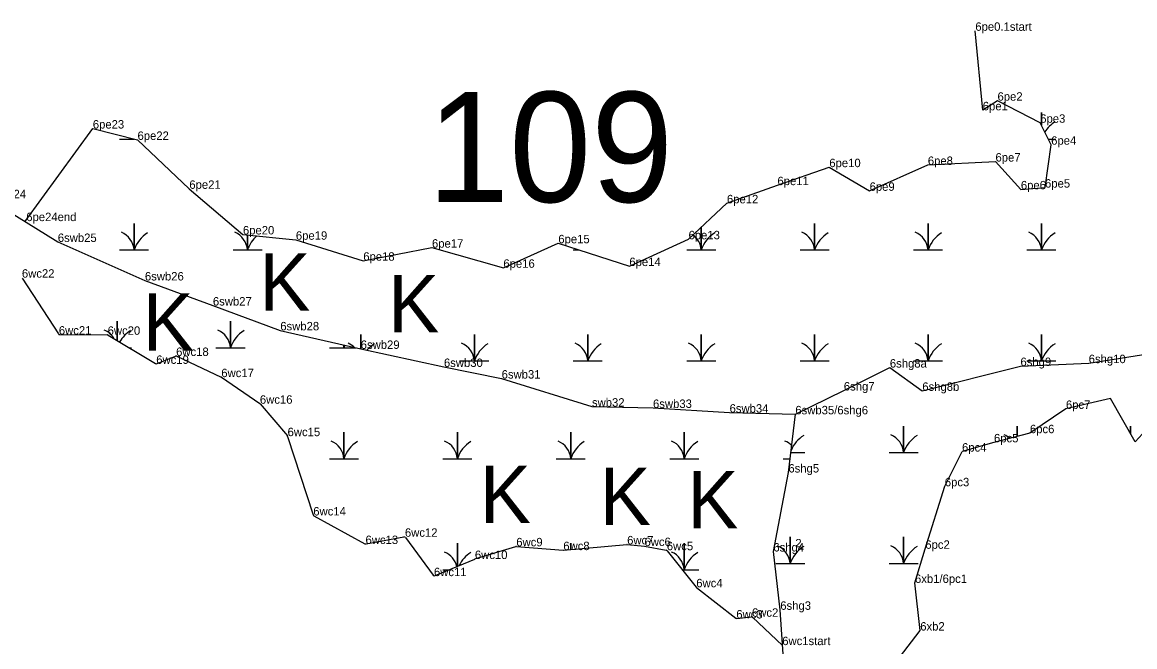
# Model space of a CAD drawing. Extents: x 2072529 to 2268796, y 436423 to 470406.
# Drawn here: x 2142381 to 2143041, y 445096 to 445467 of the extents above; entities that cross this region are included whole.
import ezdxf

# ---------------------------------------------------------------- set-up
doc = ezdxf.new("R2010")
doc.units = 0
for name, color, linetype in [('Default', 7, 'Continuous'), ('Exist Environmental Wetland Boundary Cogo Comment', 7, 'Continuous'), ('Exist Environmental Wetland Boundary Cogo Point CELL', 7, 'Continuous'), ('Exist Hydro Jurisdictional Stream or Body of Water NEU Mitigable Cogo Comment', 7, 'Continuous'), ('Old_Level_20', 7, 'Continuous'), ('Old_Level_52', 7, 'Continuous')]:
    doc.layers.add(name, color=color, linetype=linetype)

msp = doc.modelspace()

# ---------------------------------------------------------------- linework, layer by layer
at = {"layer": 'Exist Environmental Wetland Boundary Cogo Point CELL'}
for points in [[(2142985.22, 445405.66), (2142985.22, 445413.26), (2142985.22, 445405.66)], [(2142438.62, 445397.48), (2142447.22, 445397.48)], [(2142989.29, 445397.48), (2142993.82, 445397.48)], [(2142438.62, 445331.68), (2142447.22, 445331.68), (2142447.22, 445347.46), (2142447.22, 445331.68), (2142455.82, 445331.68)], [(2142774.87, 445331.68), (2142783.47, 445331.68), (2142783.47, 445345.08)], [(2142783.47, 445345.08), (2142783.47, 445331.68), (2142792.07, 445331.68)], [(2142842.12, 445331.68), (2142850.72, 445331.68), (2142850.72, 445347.46), (2142850.72, 445331.68), (2142859.32, 445331.68)], [(2142909.37, 445331.68), (2142917.97, 445331.68), (2142917.97, 445347.46), (2142917.97, 445331.68), (2142926.57, 445331.68)], [(2142976.62, 445331.68), (2142985.22, 445331.68), (2142985.22, 445347.46), (2142985.22, 445331.68), (2142993.82, 445331.68)], [(2142505.87, 445331.68), (2142514.47, 445331.68), (2142514.47, 445340.62)], [(2142514.47, 445340.62), (2142514.47, 445331.68), (2142523.07, 445331.68)], [(2142707.62, 445331.68), (2142711.16, 445331.68)], [(2142437.12, 445278.04), (2142437.12, 445289.47), (2142437.12, 445278.04)], [(2142495.77, 445273.69), (2142504.37, 445273.69), (2142504.37, 445289.47), (2142504.37, 445273.69), (2142512.97, 445273.69)], [(2142581.72, 445272.99), (2142581.72, 445281.66), (2142581.72, 445272.99)], [(2142640.37, 445265.88), (2142648.97, 445265.88), (2142648.97, 445281.66), (2142648.97, 445265.88), (2142657.57, 445265.88)], [(2142707.62, 445265.88), (2142716.22, 445265.88), (2142716.22, 445281.66), (2142716.22, 445265.88), (2142724.82, 445265.88)], [(2142774.87, 445265.88), (2142783.47, 445265.88), (2142783.47, 445281.66), (2142783.47, 445265.88), (2142792.07, 445265.88)], [(2142842.12, 445265.88), (2142850.72, 445265.88), (2142850.72, 445281.66), (2142850.72, 445265.88), (2142859.32, 445265.88)], [(2142909.37, 445265.88), (2142917.97, 445265.88), (2142917.97, 445281.66), (2142917.97, 445265.88), (2142926.57, 445265.88)], [(2142976.62, 445265.88), (2142985.22, 445265.88), (2142985.22, 445281.66), (2142985.22, 445265.88), (2142993.82, 445265.88)], [(2142444.4, 445273.69), (2142445.72, 445273.69)], [(2142563.02, 445273.69), (2142571.62, 445273.69), (2142571.62, 445275.32)], [(2142571.62, 445275.32), (2142571.62, 445273.69), (2142578.7, 445273.69)], [(2142894.87, 445211.51), (2142903.47, 445211.51), (2142903.47, 445227.29), (2142903.47, 445211.51), (2142912.07, 445211.51)], [(2142970.72, 445221.08), (2142970.72, 445227.29), (2142970.72, 445221.08)], [(2143037.97, 445222.71), (2143037.97, 445227.29), (2143037.97, 445222.71)], [(2142563.02, 445207.89), (2142571.62, 445207.89), (2142571.62, 445223.67), (2142571.62, 445207.89), (2142580.22, 445207.89)], [(2142630.27, 445207.89), (2142638.87, 445207.89), (2142638.87, 445223.67), (2142638.87, 445207.89), (2142647.47, 445207.89)], [(2142697.52, 445207.89), (2142706.12, 445207.89), (2142706.12, 445223.67), (2142706.12, 445207.89), (2142714.72, 445207.89)], [(2142764.77, 445207.89), (2142773.37, 445207.89), (2142773.37, 445223.67), (2142773.37, 445207.89), (2142781.97, 445207.89)], [(2142836.56, 445211.51), (2142844.82, 445211.51)], [(2142832.02, 445207.89), (2142836.12, 445207.89)], [(2142827.62, 445145.71), (2142836.22, 445145.71), (2142836.22, 445161.49), (2142836.22, 445145.71), (2142844.82, 445145.71)], [(2142894.87, 445145.71), (2142903.47, 445145.71), (2142903.47, 445161.49), (2142903.47, 445145.71), (2142912.07, 445145.71)], [(2142638.87, 445144.06), (2142638.87, 445157.87), (2142638.87, 445144.06)], [(2142706.12, 445154.08), (2142706.12, 445157.87), (2142706.12, 445154.08)], [(2142772.23, 445142.09), (2142773.37, 445142.09), (2142773.37, 445157.87), (2142773.37, 445142.09), (2142781.97, 445142.09)], [(2142630.27, 445142.09), (2142634.17, 445142.09)]]:
    msp.add_lwpolyline(points, dxfattribs=at)
for centre, radius, start, end in [((2143003.46, 445391.42), 19.22, 122.12745, 147.76598), ((2142434.95, 445330.79), 12.3, 4.14034, 67.53497), ((2142465.46, 445325.62), 19.22, 122.12745, 161.62219), ((2142502.2, 445330.79), 12.3, 4.14034, 67.53497), ((2142532.71, 445325.62), 19.22, 131.26844, 161.62219), ((2142771.2, 445330.79), 12.3, 4.14034, 52.66995), ((2142801.71, 445325.62), 19.22, 122.12745, 161.62219), ((2142838.45, 445330.79), 12.3, 4.14034, 67.53497), ((2142868.96, 445325.62), 19.22, 122.12745, 161.62219), ((2142905.7, 445330.79), 12.3, 4.14034, 67.53497), ((2142936.21, 445325.62), 19.22, 122.12745, 161.62219), ((2142972.95, 445330.79), 12.3, 4.14034, 67.53497), ((2143003.46, 445325.62), 19.22, 122.12745, 161.62219), ((2142424.86, 445272.8), 12.3, 30.50388, 67.53497), ((2142455.36, 445267.63), 19.22, 122.12745, 150.3865), ((2142492.11, 445272.8), 12.3, 4.14034, 67.53497), ((2142522.61, 445267.63), 19.22, 122.12745, 161.62219), ((2142559.36, 445272.8), 12.3, 4.14034, 12.09595), ((2142589.86, 445267.63), 19.22, 156.83207, 161.62219), ((2142569.45, 445264.99), 12.3, 46.08996, 67.53497), ((2142599.96, 445259.82), 19.22, 122.12745, 139.82345), ((2142636.7, 445264.99), 12.3, 4.14034, 67.53497), ((2142667.21, 445259.82), 19.22, 122.12745, 161.62219), ((2142703.95, 445264.99), 12.3, 4.14034, 67.53497), ((2142734.46, 445259.82), 19.22, 122.12745, 161.62219), ((2142771.2, 445264.99), 12.3, 4.14034, 67.53497), ((2142801.71, 445259.82), 19.22, 122.12745, 161.62219), ((2142838.45, 445264.99), 12.3, 4.14034, 67.53497), ((2142868.96, 445259.82), 19.22, 122.12745, 161.62219), ((2142905.7, 445264.99), 12.3, 4.14034, 67.53497), ((2142936.21, 445259.82), 19.22, 122.12745, 161.62219), ((2142972.95, 445264.99), 12.3, 4.14034, 67.53497), ((2143003.46, 445259.82), 19.22, 122.12745, 161.62219), ((2142559.36, 445207), 12.3, 4.14034, 67.53497), ((2142589.86, 445201.83), 19.22, 122.12745, 161.62219), ((2142626.61, 445207), 12.3, 4.14034, 67.53497), ((2142657.11, 445201.83), 19.22, 122.12745, 161.62219), ((2142693.86, 445207), 12.3, 4.14034, 67.53497), ((2142724.36, 445201.83), 19.22, 122.12745, 161.62219), ((2142761.11, 445207), 12.3, 4.14034, 67.53497), ((2142791.61, 445201.83), 19.22, 122.12745, 161.62219), ((2142828.36, 445207), 12.3, 44.98177, 67.53497), ((2142854.46, 445205.45), 19.22, 122.12745, 157.4262), ((2142891.21, 445210.62), 12.3, 4.14034, 67.53497), ((2142921.71, 445205.45), 19.22, 122.12745, 161.62219), ((2142958.46, 445210.62), 12.3, 49.6148, 67.53497), ((2142626.61, 445141.2), 12.3, 12.88474, 67.53497), ((2142657.11, 445136.03), 19.22, 122.12745, 153.96221), ((2142761.11, 445141.2), 12.3, 4.14034, 67.53497), ((2142791.61, 445136.03), 19.22, 122.12745, 161.62219), ((2142823.96, 445144.82), 12.3, 4.14034, 67.53497), ((2142854.46, 445139.65), 19.22, 122.12745, 161.62219), ((2142891.21, 445144.82), 12.3, 4.14034, 67.53497), ((2142921.71, 445139.65), 19.22, 122.12745, 161.62219)]:
    msp.add_arc(centre, radius, start, end, dxfattribs=at)
at = {"layer": 'Old_Level_20'}
for p, q in [((2142945.65, 445461.33), (2142945.65, 445461.33)), ((2142959.14, 445420.22), (2142959.14, 445420.22)), ((2142950.4, 445414.53), (2142950.4, 445414.53)), ((2142422.74, 445403.71), (2142422.74, 445403.71)), ((2142984.48, 445407.14), (2142984.48, 445407.14)), ((2142449.23, 445396.97), (2142449.23, 445396.97)), ((2142990.96, 445394.11), (2142990.96, 445394.11)), ((2142957.94, 445384.11), (2142957.94, 445384.11)), ((2142859.41, 445380.81), (2142859.41, 445380.81)), ((2142917.83, 445382.12), (2142917.83, 445382.12)), ((2142828.66, 445370.13), (2142828.66, 445370.13)), ((2142479.96, 445367.96), (2142479.96, 445367.96)), ((2142883.3, 445366.78), (2142883.3, 445366.78)), ((2142972.99, 445367.64), (2142972.99, 445367.64)), ((2142987.32, 445368.67), (2142987.32, 445368.67)), ((2142798.71, 445359.37), (2142798.71, 445359.37)), ((2142382.4, 445348.38), (2142382.4, 445348.38)), ((2142511.74, 445340.9), (2142511.74, 445340.9)), ((2142543.13, 445337.76), (2142543.13, 445337.76)), ((2142775.96, 445338.03), (2142775.96, 445338.03)), ((2142401.98, 445336.44), (2142401.98, 445336.44)), ((2142623.83, 445333.07), (2142623.83, 445333.07)), ((2142698.74, 445335.67), (2142698.74, 445335.67)), ((2142583.09, 445325.33), (2142583.09, 445325.33)), ((2142666.17, 445321.15), (2142666.17, 445321.15)), ((2142740.85, 445322.15), (2142740.85, 445322.15)), ((2142380.9, 445314.95), (2142402.29, 445281.96)), ((2142453.62, 445313.6), (2142453.62, 445313.6)), ((2142493.93, 445298.74), (2142493.93, 445298.74)), ((2142533.89, 445284.02), (2142533.89, 445284.02)), ((2142402.59, 445281.51), (2142402.59, 445281.51)), ((2142403.13, 445281.51), (2142431.26, 445281.39)), ((2142431.53, 445281.39), (2142431.53, 445281.39)), ((2142431.77, 445281.25), (2142459.91, 445264.4)), ((2142581.58, 445273.02), (2142581.58, 445273.02)), ((2142460.34, 445264.14), (2142460.34, 445264.14)), ((2142460.8, 445264.32), (2142471.73, 445268.67)), ((2142472.13, 445268.83), (2142472.13, 445268.83)), ((2142472.53, 445268.64), (2142498.84, 445256.3)), ((2143013.21, 445264.58), (2143013.21, 445264.58)), ((2142630.92, 445262.32), (2142630.92, 445262.32)), ((2142895.3, 445261.95), (2142895.3, 445261.95)), ((2142895.3, 445261.95), (2142895.3, 445261.95)), ((2142972.75, 445262.87), (2142972.75, 445262.87)), ((2142972.75, 445262.87), (2142972.75, 445262.87)), ((2142498.91, 445256.27), (2142498.91, 445256.27)), ((2142498.98, 445256.22), (2142521.68, 445240.57)), ((2142665.14, 445255.43), (2142665.14, 445255.43)), ((2142868.02, 445248.35), (2142868.02, 445248.35)), ((2142868.02, 445248.35), (2142868.02, 445248.35)), ((2142914.55, 445248.15), (2142914.55, 445248.15)), ((2142914.55, 445248.15), (2142914.55, 445248.15)), ((2142521.79, 445240.5), (2142521.79, 445240.5)), ((2142521.87, 445240.4), (2142538.07, 445221.42)), ((2142718.69, 445238.77), (2142718.69, 445238.77)), ((2142754.89, 445238.01), (2142754.89, 445238.01)), ((2142800.28, 445235.23), (2142800.28, 445235.23)), ((2142839.27, 445234.22), (2142839.27, 445234.22)), ((2142999.71, 445237.43), (2142999.71, 445237.43)), ((2142999.71, 445237.43), (2142999.71, 445237.43)), ((2142999.71, 445237.43), (2142999.71, 445237.43)), ((2142999.71, 445237.43), (2142999.71, 445237.43)), ((2142999.71, 445237.43), (2142999.71, 445237.43)), ((2142999.71, 445237.43), (2142999.71, 445237.43)), ((2142999.71, 445237.43), (2142999.71, 445237.43)), ((2142999.71, 445237.43), (2142999.71, 445237.43)), ((2142999.71, 445237.43), (2142999.71, 445237.43)), ((2142999.71, 445237.43), (2142999.71, 445237.43)), ((2142999.71, 445237.43), (2142999.71, 445237.43)), ((2142999.71, 445237.43), (2142999.71, 445237.43)), ((2142999.71, 445237.43), (2142999.71, 445237.43)), ((2142999.71, 445237.43), (2142999.71, 445237.43)), ((2142538.2, 445221.27), (2142538.2, 445221.27)), ((2142538.26, 445221.08), (2142553.31, 445174.62)), ((2142978.38, 445223.03), (2142978.38, 445223.03)), ((2142978.38, 445223.03), (2142978.38, 445223.03)), ((2142978.38, 445223.03), (2142978.38, 445223.03)), ((2142978.38, 445223.03), (2142978.38, 445223.03)), ((2142978.38, 445223.03), (2142978.38, 445223.03)), ((2142978.38, 445223.03), (2142978.38, 445223.03)), ((2142978.38, 445223.03), (2142978.38, 445223.03)), ((2142978.38, 445223.03), (2142978.38, 445223.03)), ((2142978.38, 445223.03), (2142978.38, 445223.03)), ((2142978.38, 445223.03), (2142978.38, 445223.03)), ((2142978.38, 445223.03), (2142978.38, 445223.03)), ((2142978.38, 445223.03), (2142978.38, 445223.03)), ((2142978.38, 445223.03), (2142978.38, 445223.03)), ((2142978.38, 445223.03), (2142978.38, 445223.03)), ((2142938.12, 445212.12), (2142938.12, 445212.12)), ((2142938.12, 445212.12), (2142938.12, 445212.12)), ((2142938.12, 445212.12), (2142938.12, 445212.12)), ((2142938.12, 445212.12), (2142938.12, 445212.12)), ((2142938.12, 445212.12), (2142938.12, 445212.12)), ((2142938.12, 445212.12), (2142938.12, 445212.12)), ((2142938.12, 445212.12), (2142938.12, 445212.12)), ((2142938.12, 445212.12), (2142938.12, 445212.12)), ((2142938.12, 445212.12), (2142938.12, 445212.12)), ((2142938.12, 445212.12), (2142938.12, 445212.12)), ((2142938.12, 445212.12), (2142938.12, 445212.12)), ((2142938.12, 445212.12), (2142938.12, 445212.12)), ((2142938.12, 445212.12), (2142938.12, 445212.12)), ((2142938.12, 445212.12), (2142938.12, 445212.12)), ((2142957.04, 445217.6), (2142957.04, 445217.6)), ((2142957.04, 445217.6), (2142957.04, 445217.6)), ((2142957.04, 445217.6), (2142957.04, 445217.6)), ((2142957.04, 445217.6), (2142957.04, 445217.6)), ((2142957.04, 445217.6), (2142957.04, 445217.6)), ((2142957.04, 445217.6), (2142957.04, 445217.6)), ((2142957.04, 445217.6), (2142957.04, 445217.6)), ((2142957.04, 445217.6), (2142957.04, 445217.6)), ((2142957.04, 445217.6), (2142957.04, 445217.6)), ((2142957.04, 445217.6), (2142957.04, 445217.6)), ((2142957.04, 445217.6), (2142957.04, 445217.6)), ((2142957.04, 445217.6), (2142957.04, 445217.6)), ((2142957.04, 445217.6), (2142957.04, 445217.6)), ((2142957.04, 445217.6), (2142957.04, 445217.6)), ((2142835.15, 445199.72), (2142835.15, 445199.72)), ((2142927.9, 445191.55), (2142927.9, 445191.55)), ((2142553.44, 445174.24), (2142553.44, 445174.24)), ((2142553.79, 445174.05), (2142584.11, 445157.47)), ((2142584.77, 445157.37), (2142607.16, 445161.5)), ((2142607.78, 445161.61), (2142607.78, 445161.61)), ((2142608.15, 445161.11), (2142624.54, 445138.88)), ((2142584.42, 445157.3), (2142584.42, 445157.3)), ((2142649.31, 445148.43), (2142673.63, 445155.89)), ((2142673.82, 445155.94), (2142673.82, 445155.94)), ((2142674.01, 445155.93), (2142701.6, 445153.69)), ((2142701.69, 445153.68), (2142701.69, 445153.68)), ((2142701.77, 445153.69), (2142739.46, 445157.08)), ((2142739.55, 445157.09), (2142739.55, 445157.09)), ((2142739.65, 445157.08), (2142749.79, 445156.1)), ((2142749.83, 445156.1), (2142749.83, 445156.1)), ((2142749.88, 445156.09), (2142762.71, 445153.68)), ((2142763.07, 445153.61), (2142763.07, 445153.61)), ((2142763.3, 445153.32), (2142780.46, 445131.73)), ((2142826.25, 445152.85), (2142826.25, 445152.85)), ((2142916.33, 445154.47), (2142916.33, 445154.47)), ((2142625.74, 445138.55), (2142649.22, 445148.39)), ((2142649.27, 445148.41), (2142649.27, 445148.41)), ((2142625.01, 445138.25), (2142625.01, 445138.25)), ((2142910.22, 445134.22), (2142910.22, 445134.22)), ((2142780.53, 445131.64), (2142780.53, 445131.64)), ((2142780.62, 445131.56), (2142803.94, 445113.41)), ((2142804.26, 445113.16), (2142804.26, 445113.16)), ((2142804.66, 445113.2), (2142813.12, 445114.12)), ((2142813.57, 445114.17), (2142813.57, 445114.17)), ((2142813.91, 445113.85), (2142831.74, 445097.07)), ((2142830.34, 445118.29), (2142830.34, 445118.29)), ((2142913.33, 445105.99), (2142913.33, 445105.99)), ((2142831.74, 445097.07), (2142831.74, 445097.07))]:
    msp.add_line(p, q, dxfattribs=at)
for points in [[(2142382.4, 445348.38), (2142422.74, 445403.71), (2142449.23, 445396.97), (2142479.96, 445367.96), (2142511.74, 445340.9), (2142543.13, 445337.76), (2142583.09, 445325.33), (2142623.83, 445333.07), (2142666.17, 445321.15), (2142698.74, 445335.67), (2142740.85, 445322.15), (2142775.96, 445338.03), (2142798.71, 445359.37), (2142828.66, 445370.13), (2142859.41, 445380.81), (2142883.3, 445366.78), (2142917.83, 445382.12), (2142957.94, 445384.11), (2142972.99, 445367.64), (2142987.32, 445368.67), (2142990.96, 445394.11), (2142984.48, 445407.14), (2142959.14, 445420.22), (2142950.4, 445414.53), (2142945.99, 445461.67)], [(2143092.67, 445278.13), (2143099.33, 445253.06), (2143072.13, 445243.2), (2143047.3, 445225.02), (2143040.73, 445217.84), (2143026.08, 445243.67), (2142999.71, 445237.43), (2142978.38, 445223.03), (2142957.04, 445217.6), (2142938.12, 445212.12)], [(2142891.28, 445077.43), (2142913.33, 445105.99), (2142910.22, 445134.22), (2142916.33, 445154.47), (2142927.9, 445191.55), (2142938.12, 445212.12)]]:
    msp.add_lwpolyline(points, dxfattribs=at)
for centre, start, end in [((2142403.13, 445282.5), 212.97092, 269.76839), ((2142431.25, 445280.39), 59.08775, 89.76839), ((2142460.43, 445265.25), 239.08775, 291.66395), ((2142472.1, 445267.74), 64.87754, 111.66395), ((2142498.41, 445255.4), 55.4131, 64.87755), ((2142521.11, 445239.75), 40.48576, 55.4131), ((2142537.31, 445220.77), 17.95189, 40.48576), ((2142554.27, 445174.93), 197.95189, 241.3358), ((2142607.34, 445160.52), 36.41128, 100.45739), ((2142584.59, 445158.35), 241.3358, 280.45739), ((2142673.93, 445154.93), 85.37077, 107.04974), ((2142701.69, 445154.69), 265.37077, 275.13262), ((2142739.55, 445156.08), 84.50969, 95.13262), ((2142749.69, 445155.11), 79.35578, 84.50969), ((2142762.52, 445152.7), 38.47106, 79.35578), ((2142649.61, 445147.47), 107.04974, 112.73399), ((2142625.35, 445139.47), 216.41127, 292.73399), ((2142781.24, 445132.35), 218.47106, 232.09177), ((2142804.55, 445114.2), 232.09177, 276.18957), ((2142813.22, 445113.12), 46.73492, 96.18957)]:
    msp.add_arc(centre, 1, start, end, dxfattribs=at)
at = {"layer": 'Old_Level_52'}
for points in [[(2142360.11, 445362.37), (2142401.98, 445336.44), (2142453.62, 445313.6), (2142493.93, 445298.74), (2142533.89, 445284.02), (2142581.58, 445273.02), (2142630.92, 445262.32), (2142665.14, 445255.43)], [(2142845.68, 445032.46), (2142833.82, 445065.8), (2142830.34, 445118.29), (2142826.25, 445152.85), (2142835.15, 445199.72), (2142839.27, 445234.22), (2142868.02, 445248.35), (2142895.3, 445261.95), (2142914.55, 445248.15), (2142972.75, 445262.87), (2143013.21, 445264.58), (2143052.07, 445270.71), (2143139.23, 445286.64)], [(2142665.14, 445255.43), (2142718.69, 445238.77), (2142754.89, 445238.01), (2142800.28, 445235.23), (2142839.27, 445234.22)]]:
    msp.add_lwpolyline(points, dxfattribs=at)

# ---------------------------------------------------------------- texts
at = {"layer": 'Default'}
msp.add_text('109', height=65.34, dxfattribs=at).set_placement((2142621.05, 445360.11))
at = {"layer": 'Exist Environmental Wetland Boundary Cogo Comment'}
for s, p in [('6pe0.1start', (2142945.99, 445461.67)), ('6pe2', (2142959.14, 445420.22)), ('6pe1', (2142950.4, 445414.53)), ('6pe3', (2142984.48, 445407.14)), ('6pe23', (2142422.74, 445403.71)), ('6pe22', (2142449.23, 445396.97)), ('6pe4', (2142990.96, 445394.11)), ('6pe10', (2142859.41, 445380.81)), ('6pe8', (2142917.83, 445382.12)), ('6pe7', (2142957.94, 445384.11)), ('6pe21', (2142479.96, 445367.96)), ('6pe11', (2142828.66, 445370.13)), ('6pe9', (2142883.3, 445366.78)), ('6pe6', (2142972.99, 445367.64)), ('6pe5', (2142987.32, 445368.67)), ('6pe12', (2142798.71, 445359.37)), ('6pe20', (2142511.74, 445340.9)), ('6pe13', (2142775.96, 445338.03)), ('6pe19', (2142543.13, 445337.76)), ('6pe17', (2142623.83, 445333.07)), ('6pe15', (2142698.74, 445335.67)), ('6pe18', (2142583.09, 445325.33)), ('6pe16', (2142666.17, 445321.15)), ('6pe14', (2142740.85, 445322.15)), ('6wc22', (2142380.69, 445315.27)), ('6wc21', (2142402.59, 445281.51)), ('6wc20', (2142431.53, 445281.39)), ('6wc18', (2142472.13, 445268.83)), ('6wc19', (2142460.34, 445264.14)), ('6wc17', (2142498.91, 445256.27)), ('6wc16', (2142521.79, 445240.5)), ('6pc7', (2142999.71, 445237.43)), ('6wc15', (2142538.2, 445221.27)), ('6pc6', (2142978.38, 445223.03)), ('6pc5', (2142957.04, 445217.6)), ('6pc4', (2142938.12, 445212.12)), ('6pc3', (2142927.9, 445191.55)), ('6wc14', (2142553.44, 445174.24)), ('6wc12', (2142607.78, 445161.61)), ('6wc13', (2142584.42, 445157.3)), ('6wc9', (2142673.82, 445155.94)), ('6wc8', (2142701.69, 445153.68)), ('6wc7', (2142739.55, 445157.09)), ('6wc6', (2142749.83, 445156.1)), ('6wc5', (2142763.07, 445153.61)), ('6pc2', (2142916.33, 445154.47)), ('6wc10', (2142649.27, 445148.41)), ('6wc11', (2142625.01, 445138.25)), ('6xb1/6pc1', (2142910.22, 445134.22)), ('6wc4', (2142780.53, 445131.64)), ('6wc2', (2142813.57, 445114.17)), ('6wc3', (2142804.26, 445113.16)), ('6xb2', (2142913.33, 445105.99))]:
    msp.add_text(s, height=5, dxfattribs=at).set_placement(p)
at = {"layer": 'Exist Environmental Wetland Boundary Cogo Point CELL'}
for p in [(2142521.43, 445295.61), (2142597.79, 445282.89), (2142452.27, 445272.05), (2142652.18, 445169.71), (2142723.24, 445168.65), (2142775.2, 445166.53)]:
    msp.add_text('K', height=34, dxfattribs=at).set_placement(p)
at = {"layer": 'Exist Hydro Jurisdictional Stream or Body of Water NEU Mitigable Cogo Comment'}
for s, p in [('6swb24', (2142360.11, 445362.37)), ('6pe24end', (2142383.27, 445348.81)), ('6swb25', (2142401.98, 445336.44)), ('6swb26', (2142453.62, 445313.6)), ('6swb27', (2142493.93, 445298.74)), ('6swb28', (2142533.89, 445284.02)), ('6swb29', (2142581.58, 445273.02)), ('6swb30', (2142630.92, 445262.32)), ('6shg8a', (2142895.3, 445261.95)), ('6shg9', (2142972.75, 445262.87)), ('6shg10', (2143013.21, 445264.58)), ('6swb31', (2142665.14, 445255.43)), ('6shg7', (2142868.02, 445248.35)), ('6shg8b', (2142914.55, 445248.15)), ('swb32', (2142718.69, 445238.77)), ('6swb33', (2142754.89, 445238.01)), ('6swb34', (2142800.28, 445235.23)), ('6swb35/6shg6', (2142839.27, 445234.22)), ('6shg5', (2142835.15, 445199.72)), ('2', (2142839.27, 445155.31)), ('6shg4', (2142826.25, 445152.85)), ('6shg3', (2142830.34, 445118.29)), ('6wc1start', (2142831.5, 445097.35))]:
    msp.add_text(s, height=5, dxfattribs=at).set_placement(p)

doc.saveas('drawing.dxf')
